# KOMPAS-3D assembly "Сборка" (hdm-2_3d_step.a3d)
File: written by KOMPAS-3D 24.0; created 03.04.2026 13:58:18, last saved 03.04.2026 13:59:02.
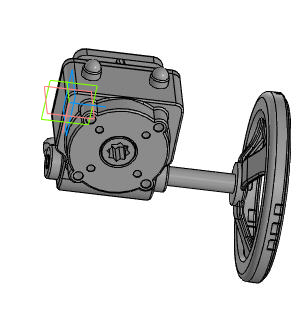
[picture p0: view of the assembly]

Document properties: Автор: R2D2; Полное имя файла: E:\Работа\Зайцев\Аксессуары для пневмоприводов\Ручной дублер DN.ru\MON2-450-T28-ISO Ручной дублер DN.ru\исходные материалы\hdm-2_3d_step.a3d

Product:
- Body: Тело 1  | qty 1
    Масса: 13.344351
- Part/product: Сборка
    Масса: 13.337265

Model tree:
1. Операция без истории:1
